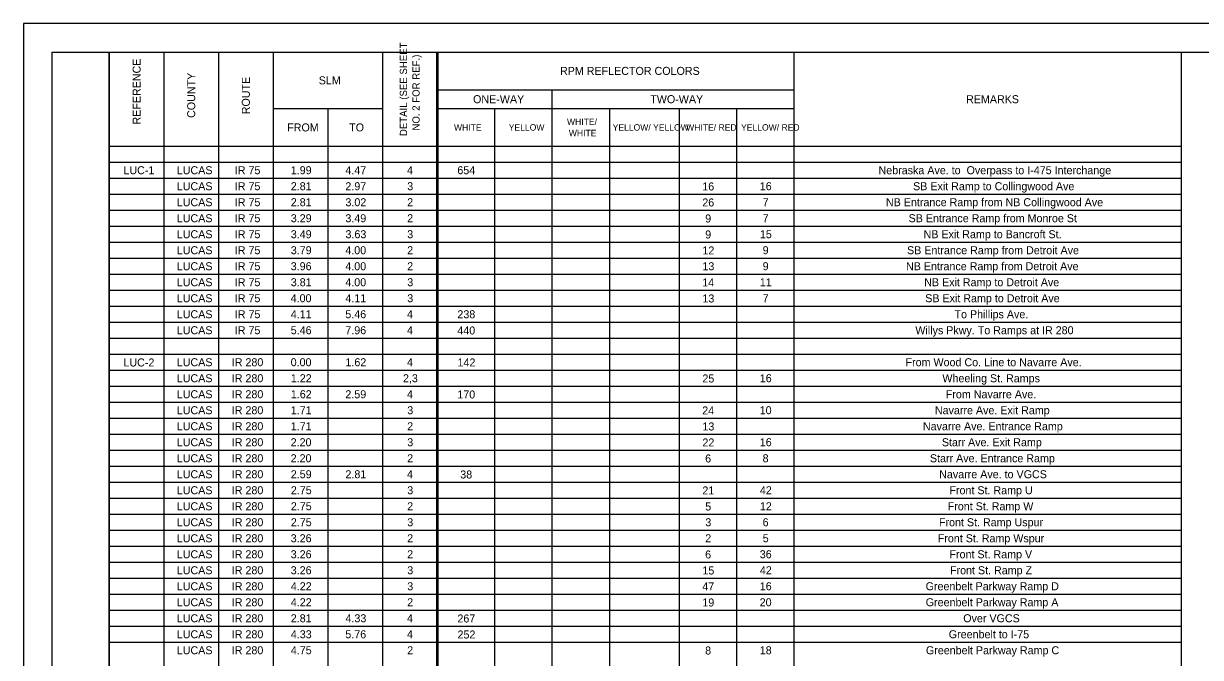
# Model space of a CAD drawing. Extents: x 0 to 34, y 0 to 22.
# Drawn here: x 0 to 20.58, y 10.91 to 22 of the extents above; entities that cross this region are included whole.
import ezdxf

# ---------------------------------------------------------------- set-up
doc = ezdxf.new("R2010")
doc.units = 0
for name, color, linetype in [('Default', 7, 'Continuous'), ('SH_Border', 7, 'Continuous'), ('SH_Cut_Line', 7, 'Continuous')]:
    doc.layers.add(name, color=color, linetype=linetype)

msp = doc.modelspace()

# ---------------------------------------------------------------- linework, layer by layer
at = {"layer": 'Default'}
for p, q in [((1.5, 21.5), (7.243, 21.5)), ((1.5, 21.5), (1.5, 19.573)), ((2.455, 21.5), (2.455, 19.853)), ((3.411, 21.5), (3.411, 19.853)), ((4.366, 21.5), (4.366, 19.853)), ((6.276, 21.5), (6.276, 19.853)), ((7.221, 21.5), (20.244, 21.5)), ((7.221, 21.5), (7.221, 1.06)), ((7.243, 21.5), (7.243, 1.06)), ((13.474, 21.5), (13.474, 19.853)), ((20.244, 21.5), (20.244, 1.06)), ((7.243, 20.841), (13.474, 20.841)), ((9.241, 20.841), (9.241, 19.853)), ((4.366, 20.512), (6.276, 20.512)), ((5.321, 20.512), (5.321, 19.853)), ((7.243, 20.512), (13.474, 20.512)), ((8.236, 20.512), (8.236, 19.853)), ((10.246, 20.512), (10.246, 19.853)), ((11.465, 20.512), (11.465, 19.853)), ((12.469, 20.512), (12.469, 19.853)), ((1.5, 19.853), (7.221, 19.853)), ((2.455, 19.853), (2.455, 1.356)), ((3.411, 19.853), (3.411, 1.356)), ((4.366, 19.853), (4.366, 1.356)), ((5.321, 19.853), (5.321, 1.356)), ((6.276, 19.853), (6.276, 1.356)), ((7.243, 19.853), (20.244, 19.853)), ((8.236, 19.853), (8.236, 1.06)), ((9.241, 19.853), (9.241, 1.06)), ((10.246, 19.853), (10.246, 1.06)), ((11.465, 19.853), (11.465, 1.06)), ((12.469, 19.853), (12.469, 1.06)), ((13.474, 19.853), (13.474, 1.06)), ((1.5, 19.573), (7.221, 19.573)), ((1.5, 19.573), (1.5, 16.773)), ((7.243, 19.573), (20.244, 19.573)), ((1.5, 19.293), (7.221, 19.293)), ((7.243, 19.293), (20.244, 19.293)), ((1.5, 19.013), (7.221, 19.013)), ((7.243, 19.013), (20.244, 19.013)), ((1.5, 18.733), (7.221, 18.733)), ((7.243, 18.733), (20.244, 18.733)), ((1.5, 18.453), (7.221, 18.453)), ((7.243, 18.453), (20.244, 18.453)), ((1.5, 18.173), (7.221, 18.173)), ((7.243, 18.173), (20.244, 18.173)), ((1.5, 17.893), (7.221, 17.893)), ((7.243, 17.893), (20.244, 17.893)), ((1.5, 17.613), (7.221, 17.613)), ((7.243, 17.613), (20.244, 17.613)), ((1.5, 17.333), (7.221, 17.333)), ((7.243, 17.333), (20.244, 17.333)), ((1.5, 17.053), (7.221, 17.053)), ((7.243, 17.053), (20.244, 17.053)), ((1.5, 16.773), (7.221, 16.773)), ((1.5, 16.773), (1.5, 1.06)), ((7.243, 16.773), (20.244, 16.773)), ((1.5, 16.493), (7.221, 16.493)), ((7.243, 16.493), (20.244, 16.493)), ((1.5, 16.213), (7.221, 16.213)), ((7.243, 16.213), (20.244, 16.213)), ((1.5, 15.933), (7.221, 15.933)), ((7.243, 15.933), (20.244, 15.933)), ((1.5, 15.653), (7.221, 15.653)), ((7.243, 15.653), (20.244, 15.653)), ((1.5, 15.373), (7.221, 15.373)), ((7.243, 15.373), (20.244, 15.373)), ((1.5, 15.093), (7.221, 15.093)), ((7.243, 15.093), (20.244, 15.093)), ((1.5, 14.813), (7.221, 14.813)), ((7.243, 14.813), (20.244, 14.813)), ((1.5, 14.533), (7.221, 14.533)), ((7.243, 14.533), (20.244, 14.533)), ((1.5, 14.253), (7.221, 14.253)), ((7.243, 14.253), (20.244, 14.253)), ((1.5, 13.973), (7.221, 13.973)), ((7.243, 13.973), (20.244, 13.973)), ((1.5, 13.693), (7.221, 13.693)), ((7.243, 13.693), (20.244, 13.693)), ((1.5, 13.413), (7.221, 13.413)), ((7.243, 13.413), (20.244, 13.413)), ((1.5, 13.133), (7.221, 13.133)), ((7.243, 13.133), (20.244, 13.133)), ((1.5, 12.853), (7.221, 12.853)), ((7.243, 12.853), (20.244, 12.853)), ((1.5, 12.573), (7.221, 12.573)), ((7.243, 12.573), (20.244, 12.573)), ((1.5, 12.293), (7.221, 12.293)), ((7.243, 12.293), (20.244, 12.293)), ((1.5, 12.013), (7.221, 12.013)), ((7.243, 12.013), (20.244, 12.013)), ((1.5, 11.733), (7.221, 11.733)), ((7.243, 11.733), (20.244, 11.733)), ((1.5, 11.453), (7.221, 11.453)), ((7.243, 11.453), (20.244, 11.453)), ((1.5, 11.173), (7.221, 11.173)), ((7.243, 11.173), (20.244, 11.173))]:
    msp.add_line(p, q, dxfattribs=at)
at = {"layer": 'SH_Border'}
for points in [[(0.5, 21.5), (1.5, 21.5), (1.5, 0.5), (0.5, 0.5)], [(1.5, 21.5), (33.5, 21.5), (33.5, 0.5), (1.5, 0.5)]]:
    msp.add_lwpolyline(points, close=True, dxfattribs=at)
at = {"layer": 'SH_Cut_Line'}
msp.add_lwpolyline([(0, 0), (34, 0), (34, 22), (0, 22)], close=True, dxfattribs=at)

# ---------------------------------------------------------------- texts
at = {"layer": 'Default'}
for s, height, p in [('DETAIL (SEE SHEET ', 0.126, (6.707, 20.03)), ('NO. 2 FOR REF.)', 0.126, (6.927, 20.127)), ('REFERENCE', 0.14, (2.048, 20.232)), ('COUNTY', 0.14, (3.003, 20.348)), ('ROUTE', 0.14, (3.958, 20.412))]:
    msp.add_text(s, height=height, rotation=90, dxfattribs=at).set_placement(p)
for s, height, p in [('RPM REFLECTOR COLORS', 0.14, (9.382, 21.101)), ('SLM', 0.14, (5.163, 20.936)), ('ONE-WAY', 0.14, (7.862, 20.606)), ('TWO-WAY', 0.14, (10.961, 20.606)), ('REMARKS', 0.14, (16.484, 20.606)), ('FROM', 0.14, (4.611, 20.112)), ('TO', 0.14, (5.695, 20.112)), ('WHITE', 0.112, (7.528, 20.126)), ('YELLOW', 0.112, (8.486, 20.126)), ('WHITE/', 0.112, (9.505, 20.224)), ('YELLOW/ YELLOW', 0.112, (10.303, 20.126)), ('WHITE/ RED', 0.112, (11.589, 20.126)), ('YELLOW/ RED', 0.112, (12.549, 20.126)), ('WHITE', 0.112, (9.537, 20.028)), ('LUC-1', 0.14, (1.747, 19.363)), ('LUCAS', 0.14, (2.68, 19.363)), ('IR 75', 0.14, (3.695, 19.363)), ('1.99', 0.14, (4.674, 19.363)), ('4.47', 0.14, (5.629, 19.363)), ('4', 0.14, (6.707, 19.363)), ('654', 0.14, (7.587, 19.363)), ('Nebraska Ave. to  Overpass to I-475 Interchange', 0.14, (14.953, 19.363)), ('LUCAS', 0.14, (2.68, 19.083)), ('IR 75', 0.14, (3.695, 19.083)), ('2.81', 0.14, (4.674, 19.083)), ('2.97', 0.14, (5.629, 19.083)), ('3', 0.14, (6.711, 19.083)), ('16', 0.14, (11.871, 19.079)), ('16', 0.14, (12.876, 19.083)), ('SB Exit Ramp to Collingwood Ave', 0.14, (15.558, 19.083)), ('LUCAS', 0.14, (2.68, 18.803)), ('IR 75', 0.14, (3.695, 18.803)), ('2.81', 0.14, (4.674, 18.803)), ('3.02', 0.14, (5.63, 18.803)), ('2', 0.14, (6.71, 18.803)), ('26', 0.14, (11.871, 18.799)), ('7', 0.14, (12.926, 18.803)), ('NB Entrance Ramp from NB Collingwood Ave', 0.14, (15.083, 18.803)), ('LUCAS', 0.14, (2.68, 18.523)), ('IR 75', 0.14, (3.695, 18.523)), ('3.29', 0.14, (4.674, 18.523)), ('3.49', 0.14, (5.629, 18.523)), ('2', 0.14, (6.71, 18.523)), ('9', 0.14, (11.922, 18.519)), ('7', 0.14, (12.926, 18.523)), ('SB Entrance Ramp from Monroe St', 0.14, (15.479, 18.523)), ('LUCAS', 0.14, (2.68, 18.243)), ('IR 75', 0.14, (3.695, 18.243)), ('3.49', 0.14, (4.674, 18.243)), ('3.63', 0.14, (5.631, 18.243)), ('3', 0.14, (6.711, 18.243)), ('9', 0.14, (11.922, 18.239)), ('15', 0.14, (12.878, 18.243)), ('NB Exit Ramp to Bancroft St.', 0.14, (15.741, 18.243)), ('LUCAS', 0.14, (2.68, 17.963)), ('IR 75', 0.14, (3.695, 17.963)), ('3.79', 0.14, (4.674, 17.963)), ('4.00', 0.14, (5.628, 17.963)), ('2', 0.14, (6.71, 17.963)), ('12', 0.14, (11.873, 17.959)), ('9', 0.14, (12.927, 17.963)), ('SB Entrance Ramp from Detroit Ave', 0.14, (15.452, 17.963)), ('LUCAS', 0.14, (2.68, 17.683)), ('IR 75', 0.14, (3.695, 17.683)), ('3.96', 0.14, (4.673, 17.683)), ('4.00', 0.14, (5.628, 17.683)), ('2', 0.14, (6.71, 17.683)), ('13', 0.14, (11.873, 17.683)), ('9', 0.14, (12.927, 17.683)), ('NB Entrance Ramp from Detroit Ave', 0.14, (15.434, 17.683)), ('LUCAS', 0.14, (2.68, 17.403)), ('IR 75', 0.14, (3.695, 17.403)), ('3.81', 0.14, (4.674, 17.403)), ('4.00', 0.14, (5.628, 17.403)), ('3', 0.14, (6.711, 17.403)), ('14', 0.14, (11.87, 17.399)), ('11', 0.14, (12.877, 17.403)), ('NB Exit Ramp to Detroit Ave', 0.14, (15.752, 17.403)), ('LUCAS', 0.14, (2.68, 17.123)), ('IR 75', 0.14, (3.695, 17.123)), ('4.00', 0.14, (4.672, 17.123)), ('4.11', 0.14, (5.63, 17.123)), ('3', 0.14, (6.711, 17.123)), ('13', 0.14, (11.873, 17.119)), ('7', 0.14, (12.926, 17.123)), ('SB Exit Ramp to Detroit Ave', 0.14, (15.77, 17.123)), ('LUCAS', 0.14, (2.68, 16.843)), ('IR 75', 0.14, (3.695, 16.843)), ('4.11', 0.14, (4.674, 16.843)), ('5.46', 0.14, (5.628, 16.843)), ('4', 0.14, (6.707, 16.843)), ('238', 0.14, (7.588, 16.843)), ('To Phillips Ave.', 0.14, (16.282, 16.843)), ('LUCAS', 0.14, (2.68, 16.563)), ('IR 75', 0.14, (3.695, 16.563)), ('5.46', 0.14, (4.673, 16.563)), ('7.96', 0.14, (5.628, 16.563)), ('4', 0.14, (6.707, 16.563)), ('440', 0.14, (7.587, 16.559)), ('Willys Pkwy. To Ramps at IR 280', 0.14, (15.597, 16.563)), ('LUC-2', 0.14, (1.747, 15.999)), ('LUCAS', 0.14, (2.68, 16.003)), ('IR 280', 0.14, (3.642, 16.003)), ('0.00', 0.14, (4.672, 16.003)), ('1.62', 0.14, (5.63, 16.003)), ('4', 0.14, (6.707, 16.003)), ('142', 0.14, (7.59, 15.999)), ('From Wood Co. Line to Navarre Ave.', 0.14, (15.426, 16.003)), ('LUCAS', 0.14, (2.68, 15.723)), ('IR 280', 0.14, (3.642, 15.723)), ('1.22', 0.14, (4.675, 15.723)), ('2,3', 0.14, (6.636, 15.723)), ('25', 0.14, (11.873, 15.719)), ('16', 0.14, (12.876, 15.723)), ('Wheeling St. Ramps', 0.14, (16.07, 15.723)), ('LUCAS', 0.14, (2.68, 15.443)), ('IR 280', 0.14, (3.642, 15.443)), ('1.62', 0.14, (4.675, 15.443)), ('2.59', 0.14, (5.629, 15.443)), ('4', 0.14, (6.707, 15.443)), ('170', 0.14, (7.587, 15.439)), ('From Navarre Ave.', 0.14, (16.13, 15.443)), ('LUCAS', 0.14, (2.68, 15.163)), ('IR 280', 0.14, (3.642, 15.163)), ('1.71', 0.14, (4.674, 15.163)), ('3', 0.14, (6.711, 15.163)), ('24', 0.14, (11.87, 15.159)), ('10', 0.14, (12.875, 15.163)), ('Navarre Ave. Exit Ramp', 0.14, (15.939, 15.163)), ('LUCAS', 0.14, (2.68, 14.883)), ('IR 280', 0.14, (3.642, 14.883)), ('1.71', 0.14, (4.674, 14.883)), ('2', 0.14, (6.71, 14.883)), ('13', 0.14, (11.873, 14.879)), ('Navarre Ave. Entrance Ramp', 0.14, (15.73, 14.883)), ('LUCAS', 0.14, (2.68, 14.603)), ('IR 280', 0.14, (3.642, 14.603)), ('2.20', 0.14, (4.672, 14.603)), ('3', 0.14, (6.711, 14.603)), ('22', 0.14, (11.873, 14.599)), ('16', 0.14, (12.876, 14.603)), ('Starr Ave. Exit Ramp', 0.14, (16.061, 14.603)), ('LUCAS', 0.14, (2.68, 14.323)), ('IR 280', 0.14, (3.642, 14.323)), ('2.20', 0.14, (4.672, 14.323)), ('2', 0.14, (6.71, 14.323)), ('6', 0.14, (11.921, 14.319)), ('8', 0.14, (12.926, 14.323)), ('Starr Ave. Entrance Ramp', 0.14, (15.852, 14.323)), ('LUCAS', 0.14, (2.68, 14.043)), ('IR 280', 0.14, (3.642, 14.043)), ('2.59', 0.14, (4.674, 14.043)), ('2.81', 0.14, (5.63, 14.043)), ('4', 0.14, (6.707, 14.043)), ('38', 0.14, (7.638, 14.039)), ('Navarre Ave. to VGCS', 0.14, (16.014, 14.043)), ('LUCAS', 0.14, (2.68, 13.763)), ('IR 280', 0.14, (3.642, 13.763)), ('2.75', 0.14, (4.675, 13.763)), ('3', 0.14, (6.711, 13.763)), ('21', 0.14, (11.872, 13.759)), ('42', 0.14, (12.878, 13.763)), ('Front St. Ramp U', 0.14, (16.193, 13.763)), ('LUCAS', 0.14, (2.68, 13.483)), ('IR 280', 0.14, (3.642, 13.483)), ('2.75', 0.14, (4.675, 13.483)), ('2', 0.14, (6.71, 13.483)), ('5', 0.14, (11.923, 13.479)), ('12', 0.14, (12.878, 13.483)), ('Front St. Ramp W', 0.14, (16.163, 13.483)), ('LUCAS', 0.14, (2.68, 13.203)), ('IR 280', 0.14, (3.642, 13.203)), ('2.75', 0.14, (4.675, 13.203)), ('3', 0.14, (6.711, 13.203)), ('3', 0.14, (11.924, 13.203)), ('6', 0.14, (12.926, 13.203)), ('Front St. Ramp Uspur', 0.14, (16.01, 13.203)), ('LUCAS', 0.14, (2.68, 12.923)), ('IR 280', 0.14, (3.642, 12.923)), ('3.26', 0.14, (4.673, 12.923)), ('2', 0.14, (6.71, 12.923)), ('2', 0.14, (11.923, 12.923)), ('5', 0.14, (12.928, 12.923)), ('Front St. Ramp Wspur', 0.14, (15.989, 12.923)), ('LUCAS', 0.14, (2.68, 12.643)), ('IR 280', 0.14, (3.642, 12.643)), ('3.26', 0.14, (4.673, 12.643)), ('2', 0.14, (6.71, 12.643)), ('6', 0.14, (11.921, 12.639)), ('36', 0.14, (12.876, 12.643)), ('Front St. Ramp V', 0.14, (16.194, 12.643)), ('LUCAS', 0.14, (2.68, 12.363)), ('IR 280', 0.14, (3.642, 12.363)), ('3.26', 0.14, (4.673, 12.363)), ('3', 0.14, (6.711, 12.363)), ('15', 0.14, (11.873, 12.359)), ('42', 0.14, (12.878, 12.363)), ('Front St. Ramp Z', 0.14, (16.203, 12.363)), ('LUCAS', 0.14, (2.68, 12.083)), ('IR 280', 0.14, (3.642, 12.083)), ('4.22', 0.14, (4.675, 12.083)), ('3', 0.14, (6.711, 12.083)), ('47', 0.14, (11.871, 12.079)), ('16', 0.14, (12.876, 12.083)), ('Greenbelt Parkway Ramp D', 0.14, (15.777, 12.083)), ('LUCAS', 0.14, (2.68, 11.803)), ('IR 280', 0.14, (3.642, 11.803)), ('4.22', 0.14, (4.675, 11.803)), ('2', 0.14, (6.71, 11.803)), ('19', 0.14, (11.872, 11.799)), ('20', 0.14, (12.875, 11.803)), ('Greenbelt Parkway Ramp A', 0.14, (15.779, 11.803)), ('LUCAS', 0.14, (2.68, 11.523)), ('IR 280', 0.14, (3.642, 11.523)), ('2.81', 0.14, (4.674, 11.523)), ('4.33', 0.14, (5.631, 11.523)), ('4', 0.14, (6.707, 11.523)), ('267', 0.14, (7.588, 11.519)), ('Over VGCS', 0.14, (16.435, 11.523)), ('LUCAS', 0.14, (2.68, 11.243)), ('IR 280', 0.14, (3.642, 11.243)), ('4.33', 0.14, (4.675, 11.243)), ('5.76', 0.14, (5.628, 11.243)), ('4', 0.14, (6.707, 11.243)), ('252', 0.14, (7.59, 11.239)), ('Greenbelt to I-75', 0.14, (16.182, 11.243)), ('LUCAS', 0.14, (2.68, 10.963)), ('IR 280', 0.14, (3.642, 10.963)), ('4.75', 0.14, (4.675, 10.963)), ('2', 0.14, (6.71, 10.963)), ('8', 0.14, (11.921, 10.959)), ('18', 0.14, (12.876, 10.963)), ('Greenbelt Parkway Ramp C', 0.14, (15.782, 10.963))]:
    msp.add_text(s, height=height, dxfattribs=at).set_placement(p)

doc.saveas('drawing.dxf')
